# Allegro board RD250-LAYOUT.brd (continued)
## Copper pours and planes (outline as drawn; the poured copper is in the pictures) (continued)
VCC12R0_1 on BOTTOM: 133.45,6.1 133.34,6.14 133.3,6.25 133.3,6.7 133.34,6.81 133.45,6.85 134.6,6.85 134.71,6.81 134.75,6.7 134.75,6.25 134.71,6.14 134.6,6.1
VCC12R0_1 on BOTTOM: 184.25,51.55 184.16,51.57 184.02,51.71 184,51.8 184,52.75 184.01,52.83 184.05,52.9 184.05,56.35 179.27,61.12 179.22,61.2 179.2,61.3 179.2,70.95 179.16,71 179.15,71.06 179.15,71.35 179.19,71.46 179.3,71.5 179.6,71.5 179.71,71.46 179.75,71.35 179.75,71.06 179.74,71 179.71,70.96 179.7,61.4 184.48,56.63 184.53,56.55 184.55,56.45 184.55,52.9 184.59,52.83 184.6,52.75 184.6,51.8 184.53,51.62 184.35,51.55
VCC12R0_1 on BOTTOM: 97.09,65.55 96.99,65.59 96.94,65.67 96.9,65.95 96.9,66.29 96.9,66.32 96.97,66.75 96.97,67.19 96.51,68.25 96.59,68.45 96.79,68.37 96.96,67.97 97.44,67.97 97.61,68.37 97.81,68.45 97.89,68.25 97.35,67.02 97.35,65.95 97.35,65.91 97.31,65.67 97.26,65.59 97.16,65.55
VCC12R0_1 on CONDUCTIVE4: outline of 178 points within 96.77,4.43 203.15,103.79
VCC12R0_2 on TOP: 234.32,5.57 234.03,5.87 234.32,6.17 235.02,6.17 235.51,6.12 239.82,6.12 243.57,9.88 243.65,9.93 243.75,9.95 244.9,9.95 248.45,13.5 248.45,13.59 248.47,13.69 248.52,13.77 248.53,13.78 248.61,13.83 248.7,13.85 248.9,13.85 248.99,13.83 249.07,13.78 249.1,13.75 254,13.75 254.1,13.73 254.18,13.68 255.05,12.8 256.45,12.8 258.4,14.75 258.4,26.6 257.87,27.13 257.82,27.21 257.8,27.3 257.8,30.15 257.87,30.33 258.05,30.4 260.35,30.4 260.53,30.33 260.6,30.15 260.6,29.65 260.87,29.38 260.9,29.35 262.19,29.35 263.35,30.09 263.62,30.21 263.91,30.25 265.2,30.25 266.25,29.2 265.2,28.15 263.91,28.15 263.62,28.19 263.35,28.31 262.19,29.05 260.9,29.05 260.87,29.02 260.6,28.75 260.6,26.75 260.53,26.57 260.35,26.5 258.9,26.5 258.9,14.65 258.88,14.55 258.83,14.47 256.73,12.37 256.67,12.33 256.61,12.31 256.58,12.3 256.55,12.3 254.95,12.3 254.85,12.32 254.77,12.37 253.9,13.25 248.9,13.25 245.18,9.52 245.1,9.47 245,9.45 243.85,9.45 240.1,5.69 240.02,5.64 239.92,5.62 235.51,5.62 235.02,5.57
VCC12R0_2 on BOTTOM: 290.56,6.38 290.5,6.39 290.46,6.42 290.09,6.78 290.06,6.83 290.05,6.89 290.05,13.89 276.54,27.4 260.95,27.4 260.25,26.7 260.08,26.59 259.89,26.55 258.75,26.55 258.4,26.7 258.25,27.05 258.25,28.75 258.4,29.1 258.75,29.25 259.89,29.25 260.08,29.21 260.25,29.1 260.95,28.4 276.75,28.4 276.94,28.36 277.1,28.25 291.4,13.96 291.51,13.79 291.55,13.6 291.55,9 292.19,8.36 293.71,8.36 293.88,8.33 294.03,8.24 294.04,8.23 294.48,7.79 294.51,7.75 294.52,7.69 294.52,6.96 294.51,6.9 294.48,6.86 294.04,6.42 293.99,6.39 293.94,6.38
VCC12R0_2 on CONDUCTIVE3: outline of 82 points within 235.95,26.4 260.1,124.15
ACIN on BOTTOM: 108.92,19.79 108.81,19.8 107.7,20.24 107.68,20.24 106.7,19.84 106.58,19.81 106.47,19.8 106.09,19.8 105.49,20.4 106.09,21 106.47,21 106.58,20.99 106.7,20.96 107.7,20.55 107.71,20.55 108.7,20.95 108.81,20.98 108.92,20.99 109.3,20.99 109.9,20.39 109.3,19.79
CONN002 on TOP, BOTTOM: 169,84.85 168.89,84.89 168.85,85 168.85,87.2 168.89,87.31 169,87.35 171.2,87.35 171.31,87.31 171.35,87.2 171.35,85 171.31,84.89 171.2,84.85
CONN002 on TOP, BOTTOM: 144.66,84.85 144.55,84.89 144.51,85 144.51,87.2 144.55,87.31 144.66,87.35 146.86,87.35 146.97,87.31 147.01,87.2 147.01,85 146.97,84.89 146.86,84.85
CONN002 on CONDUCTIVE2, CONDUCTIVE5: 163.8,73.35 163.73,73.38 163.7,73.45 163.7,74.8 163.49,75.29 163,75.5 161.84,75.5 161.8,75.51 161.77,75.53 161.1,76.2 156.68,76.2 156.6,76.23 156.57,76.3 156.57,76.92 151.7,81.8 147.94,81.8 147.9,81.81 147.87,81.83 144.68,85.02 144.66,85.05 144.65,85.09 144.65,86.9 144.68,86.97 144.75,87 146.85,87 146.92,86.97 146.95,86.9 146.95,84.6 148.88,82.67 156.33,82.67 156.37,82.67 156.4,82.65 159.35,79.7 167.2,79.7 167.27,79.67 167.3,79.6 167.3,75.84 167.29,75.8 167.27,75.77 167.15,75.65 167.15,73.45 167.12,73.38 167.05,73.35
CONN002 on CONDUCTIVE3, CONDUCTIVE4: outline of 88 points within 143.97,62.8 200,112.1
CONN003 on BOTTOM: outline of 86 points within 169.15,84.9 199.95,129.4
CONN004 on TOP: 293.96,109.55 293.9,109.56 293.86,109.59 293.29,110.16 293.26,110.2 293.25,110.26 293.25,116.79 293.26,116.85 293.29,116.89 293.86,117.46 293.9,117.49 293.96,117.5 300.89,117.5 300.95,117.49 300.99,117.46 301.41,117.04 301.44,117 301.45,116.94 301.45,110.21 301.44,110.15 301.41,110.11 300.89,109.59 300.85,109.56 300.79,109.55
CONN004 on TOP: 305.6,44.85 305.49,44.89 305.45,45 305.45,46.64 305.44,46.7 305.41,46.74 302.82,49.33 294.51,49.33 294.45,49.34 294.41,49.37 293.14,50.63 293.11,50.68 293.1,50.74 293.1,69.84 293.11,69.9 293.14,69.94 293.76,70.56 293.8,70.59 293.86,70.6 303.65,70.6 303.76,70.56 303.8,70.45 303.8,63.25 306.2,60.85 314.95,60.85 315.06,60.81 315.1,60.7 315.1,49.55 315.36,49.29 315.39,49.25 315.4,49.19 315.4,45 315.36,44.89 315.25,44.85 312.35,44.85 312.24,44.89 312.2,45 312.2,46.7 311.9,47 309.05,47 308.7,46.65 308.7,45 308.66,44.89 308.55,44.85
CONN004 on TOP: 277.95,77 277.84,77.04 277.8,77.15 277.8,85.3 277.84,85.41 277.95,85.45 280.7,85.45 280.81,85.41 280.85,85.3 280.85,77.15 280.81,77.04 280.7,77
CONN004 on TOP: 278,123.1 277.89,123.14 277.85,123.25 277.85,131.4 277.89,131.51 278,131.55 280.7,131.55 280.81,131.51 280.85,131.4 280.85,123.25 280.81,123.14 280.7,123.1
CONN004 on BOTTOM: outline of 110 points within 278.75,44.85 317.95,129.3 ; 5 cut-outs
CONN004 on CONDUCTIVE3: 278.85,81.49 278.86,81.55 278.89,81.59 279.48,82.18 279.53,82.21 279.59,82.22 283.26,82.22 283.32,82.21 283.37,82.18 284.95,80.6 300.85,80.6 302.65,82.4 302.65,91.65 299.57,94.73 296.18,94.73 296.07,94.78 293.29,97.56 293.26,97.6 293.25,97.66 293.25,116.2 290.45,119 279.81,119 279.75,119.01 279.71,119.04 278.79,119.96 278.76,120 278.75,120.06 278.75,128.09 278.76,128.15 278.79,128.19 279.86,129.26 279.9,129.29 279.96,129.3 283.14,129.3 283.2,129.29 283.24,129.26 284.8,127.7 301.41,127.7 301.45,127.69 301.48,127.67 306.6,122.55 317.8,122.55 317.91,122.51 317.95,122.4 317.95,72.86 317.94,72.8 317.91,72.76 315.99,70.84 315.95,70.81 315.89,70.8 312.45,70.8 311.65,70 311.65,66.7 313.92,64.43 313.94,64.4 313.95,64.36 313.95,49.45 313.92,49.38 313.85,49.35 296.94,49.35 296.9,49.36 296.87,49.38 293.14,53.11 293.11,53.15 293.1,53.21 293.1,74.05 292.32,74.83 282.12,74.83 282.08,74.83 282.05,74.85 278.89,78.01 278.86,78.05 278.85,78.11 ; 5 cut-outs
CONN004 on CONDUCTIVE4: outline of 95 points within 278.75,44.85 317.95,129.3 ; 5 cut-outs
CS on BOTTOM: 245.85,42 245.74,42.04 245.7,42.15 245.7,45.2 245.74,45.31 245.85,45.35 248.3,45.35 248.41,45.31 248.45,45.2 248.45,42.15 248.41,42.04 248.3,42
CSB on BOTTOM: 131.71,85.24 131.71,85.6 131.43,86.25 131.41,86.35 131.41,87.2 131.62,87.58 132.05,87.61 132.44,87.43 132.55,87.43 132.75,87.63 132.8,87.66 132.86,87.67 133.04,87.67 133.42,87.79 133.46,87.8 133.5,87.8 133.7,87.8 133.97,87.53 133.7,87.25 133.5,87.25 133.46,87.25 133.42,87.26 133.04,87.38 132.96,87.38 132.68,87.1 132.64,87.06 132.31,86.91 132.31,86.35 132.3,86.25 132.05,85.68 132.05,85.36 132.16,84.98 132.17,84.91 132.14,84.85 132.06,84.79 131.95,84.8 131.94,84.81 131.9,84.79 131.86,84.79 131.82,84.79 131.67,84.83 131.64,84.98
FG1 on BOTTOM: 26.21,41.22 26.21,41.29 26.5,43.25 26.5,65.6 26.58,65.98 26.79,66.31 32.69,72.21 33.02,72.42 33.4,72.5 48.1,72.5 52.56,76.96 52.6,76.99 52.66,77 54.94,77 55,76.99 55.04,76.96 56.06,75.94 56.09,75.9 56.1,75.84 56.1,67.6 63.53,60.17 63.56,60.12 63.57,60.07 63.57,50.06 63.56,50 63.53,49.95 62.82,49.24 62.77,49.21 62.71,49.2 54.86,49.2 54.8,49.21 54.76,49.24 50.14,53.86 50.11,53.9 50.1,53.96 50.1,68.3 47.9,70.5 33.81,70.5 28.5,65.19 28.5,43.25 28.79,41.29 28.79,41.22 28.8,41.14 28.39,40.34 27.5,40.19 26.61,40.34 26.2,41.14
HS1_2 on BOTTOM (solid shape): 173.56,130 173.76,130.28 174.05,130.08 174.24,128.95 174.81,125.58 174.74,125.36 174.52,125.29 171.15,125.86 170.02,126.05 169.87,126.13 169.81,126.29 169.9,126.49 170.1,126.54 171.1,126.37 173.73,129
LGND on TOP: 267.05,64.3 266.94,64.34 266.9,64.45 266.9,67.7 265.44,69.16 265.41,69.2 265.4,69.26 265.4,69.7 265,70.1 262.5,70.1 262.39,70.14 262.35,70.25 262.35,73.15 262.39,73.26 262.5,73.3 263.4,73.3 263.75,73.65 263.75,74.24 263.76,74.3 263.79,74.34 264.21,74.76 264.25,74.79 264.31,74.8 265.75,74.8 267.05,76.1 267.05,76.15 267.09,76.26 267.2,76.3 270.55,76.3 270.66,76.26 270.7,76.15 270.7,66.11 270.69,66.05 270.66,66.01 268.99,64.34 268.95,64.31 268.89,64.3
LGND on TOP: 267.05,102.4 266.94,102.44 266.9,102.55 266.9,105.8 265.44,107.26 265.41,107.3 265.4,107.36 265.4,107.8 265,108.2 262.5,108.2 262.39,108.24 262.35,108.35 262.35,111.25 262.39,111.36 262.5,111.4 263.4,111.4 263.75,111.75 263.75,112.34 263.76,112.4 263.79,112.44 264.21,112.86 264.25,112.89 264.31,112.9 265.95,112.9 267.02,113.97 267.02,114.25 267.07,114.36 267.18,114.4 270.55,114.4 270.66,114.36 270.7,114.25 270.7,104.21 270.69,104.15 270.66,104.11 268.99,102.44 268.95,102.41 268.89,102.4
LGND on TOP: 242.81,15.7 242.75,15.71 242.71,15.74 241.2,17.25 238.31,17.25 238.25,17.26 238.21,17.29 237.89,17.61 237.86,17.65 237.85,17.71 237.85,21.74 237.86,21.8 237.89,21.84 238.11,22.06 238.15,22.09 238.21,22.1 241.84,22.1 241.9,22.09 241.94,22.06 243.9,20.1 248.19,20.1 248.25,20.09 248.29,20.06 248.8,19.55 255.35,19.55 255.46,19.51 255.5,19.4 255.5,15.85 255.46,15.74 255.35,15.7
LGND on TOP: 317.95,12.25 317.91,12.14 317.8,12.1 295.15,12.1 295.04,12.14 295,12.25 295,23.7 295.04,23.81 295.15,23.85 317.8,23.85 317.91,23.81 317.95,23.7 ; 1 cut-out
LGND on TOP: outline of 146 points within 262.15,49.83 317.9,134.45 ; 2 cut-outs
LGND on TOP: 266.85,4.9 266.74,4.94 266.7,5.05 266.7,11.95 266.74,12.06 266.85,12.1 267.76,12.1 267.85,12.07 267.9,12 272.5,7.4 272.53,7.35 272.54,7.3 272.54,5.55 272.53,5.49 272.5,5.44 272,4.94 271.95,4.91 271.89,4.9
LGND on BOTTOM: 269.06,5.45 269,5.46 268.96,5.49 267.45,7 266.25,7 266.14,7.04 266.1,7.15 266.1,7.45 266.14,7.56 266.25,7.6 266.8,7.6 267.1,7.9 267.1,8.54 267.11,8.6 267.14,8.64 267.16,8.66 267.2,8.69 267.26,8.7 268.14,8.7 268.2,8.69 268.24,8.66 269.5,7.4 271.84,7.4 271.9,7.39 271.94,7.36 272.21,7.09 272.24,7.05 272.25,6.99 272.25,5.96 272.24,5.9 272.21,5.86 271.84,5.49 271.8,5.46 271.74,5.45
LGND on BOTTOM: 246.9,80.05 246.79,80.09 246.75,80.2 246.75,81.35 246.79,81.46 246.9,81.5 247.99,81.5 248.05,81.49 248.09,81.46 248.55,81 250.25,81 251.4,82.15 251.4,82.95 250.91,83.44 244.06,83.44 244,83.45 243.96,83.48 243.83,83.61 243.8,83.65 243.79,83.71 243.79,84.14 243.8,84.2 243.83,84.24 243.91,84.32 243.95,84.35 244.01,84.36 251.73,84.36 251.79,84.35 251.83,84.32 252.16,83.99 252.19,83.95 252.2,83.89 252.2,80.71 252.19,80.65 252.16,80.61 252.04,80.49 252,80.46 251.94,80.45 248.55,80.45 248.19,80.09 248.15,80.06 248.09,80.05
LGND on BOTTOM: 246.9,118.15 246.79,118.19 246.75,118.3 246.75,119.45 246.79,119.56 246.9,119.6 247.99,119.6 248.05,119.59 248.09,119.56 248.55,119.1 250.25,119.1 251.4,120.25 251.4,121.05 250.91,121.54 244.06,121.54 244,121.55 243.96,121.58 243.83,121.71 243.8,121.75 243.79,121.81 243.79,122.24 243.8,122.3 243.83,122.34 243.91,122.42 243.95,122.45 244.01,122.46 251.73,122.46 251.79,122.45 251.83,122.42 252.16,122.09 252.19,122.05 252.2,121.99 252.2,118.81 252.19,118.75 252.16,118.71 252.04,118.59 252,118.56 251.94,118.55 248.55,118.55 248.19,118.19 248.15,118.16 248.09,118.15
LGND on BOTTOM: outline of 105 points within 262.35,107.25 305.6,134.5 ; 2 cut-outs
LGND on BOTTOM: 262.2,3 262.09,3.04 262.05,3.15 262.05,4.2 262.09,4.31 262.2,4.35 262.85,4.35 262.96,4.31 263,4.2 263,3.15 262.96,3.04 262.85,3
LGND on BOTTOM: 285.56,6.33 285.5,6.34 285.46,6.37 285.14,6.68 285.11,6.73 285.1,6.79 285.1,7.94 285.11,8 285.14,8.04 285.41,8.31 285.45,8.34 285.51,8.35 287.4,8.35 288.05,9 288.05,12.19 282.09,18.15 257,18.15 254.89,16.04 254.85,16.01 254.79,16 240.91,16 240.85,16.01 240.81,16.04 239.25,17.6 238.31,17.6 238.25,17.61 238.21,17.64 238.06,17.79 238.03,17.83 238.02,17.89 238.02,21.24 238.03,21.3 238.06,21.34 238.41,21.69 238.46,21.72 238.52,21.74 239.29,21.74 239.35,21.72 239.39,21.69 240.64,20.45 257.19,20.45 257.25,20.43 257.3,20.4 258.55,19.15 282.3,19.15 282.43,19.13 282.65,19 288.9,12.76 289.01,12.59 289.05,12.4 289.05,8.74 289.41,7.49 289.41,7.46 289.42,7.4 289.42,6.81 289.41,6.75 289.38,6.71 289.04,6.37 289,6.34 288.94,6.33
LGND on BOTTOM: outline of 114 points within 262.35,69.15 301.65,96 ; 2 cut-outs
LGND on BOTTOM: 249.5,2.4 249.39,2.44 249.35,2.55 249.35,6.25 249.39,6.36 249.5,6.4 251.05,6.4 251.16,6.36 251.2,6.25 251.2,2.55 251.16,2.44 251.05,2.4
LGND on BOTTOM: 258.65,119 258.54,119.04 258.5,119.15 258.5,122.85 258.54,122.96 258.65,123 261.7,123 261.81,122.96 261.85,122.85 261.85,119.15 261.81,119.04 261.7,119
LGND on BOTTOM: 287.3,23 287.19,23.04 287.15,23.15 287.15,24.85 287.19,24.96 287.3,25 289.3,25 289.41,24.96 289.45,24.85 289.45,23.15 289.41,23.04 289.3,23
LGND on BOTTOM: 258.65,80.9 258.54,80.94 258.5,81.05 258.5,84.4 258.54,84.51 258.65,84.55 261.7,84.55 261.81,84.51 261.85,84.4 261.85,81.05 261.81,80.94 261.7,80.9
LGND on CONDUCTIVE2, CONDUCTIVE5: 246,86.98 246.03,87.05 246.1,87.08 253.93,87.08 256.62,89.77 256.65,89.79 256.69,89.8 261.95,89.8 262.35,90.2 262.35,94.5 262.38,94.57 262.45,94.6 265.2,94.6 265.27,94.57 265.3,94.5 265.3,70.2 265.27,70.13 265.2,70.1 262.45,70.1 262.38,70.13 262.35,70.2 262.35,74.7 261.75,75.3 256.84,75.3 256.8,75.31 256.77,75.33 256.63,75.47 256.61,75.5 256.6,75.54 256.6,77.7 255.15,79.15 252.24,79.15 252.2,79.16 252.17,79.18 250.93,80.42 250.91,80.45 250.9,80.49 250.9,83 250.45,83.45 246.1,83.45 246.03,83.48 246,83.55 ; 2 cut-outs
LGND on CONDUCTIVE2, CONDUCTIVE5: 245.2,79.85 245.13,79.88 245.1,79.95 245.1,82.35 245.13,82.42 245.2,82.45 250.1,82.45 250.17,82.42 250.2,82.35 250.2,79.95 250.17,79.88 250.1,79.85
LGND on CONDUCTIVE2, CONDUCTIVE5: outline of 187 points within 233.95,0.6 317.95,134.45 ; 51 cut-outs
LGND on CONDUCTIVE2, CONDUCTIVE5: 246,125.08 246.03,125.15 246.1,125.17 253.93,125.17 256.62,127.87 256.65,127.89 256.69,127.9 260.45,127.9 262.35,129.8 262.35,132.6 262.38,132.67 262.45,132.7 265.2,132.7 265.27,132.67 265.3,132.6 265.3,108.3 265.27,108.23 265.2,108.2 262.45,108.2 262.38,108.23 262.35,108.3 262.35,112.15 261.1,113.4 256.84,113.4 256.8,113.41 256.77,113.43 256.63,113.57 256.61,113.6 256.6,113.64 256.6,115.8 255.15,117.25 252.24,117.25 252.2,117.26 252.17,117.28 250.93,118.52 250.91,118.55 250.9,118.59 250.9,121.1 250.45,121.55 246.1,121.55 246.03,121.58 246,121.65 ; 2 cut-outs
LGND on CONDUCTIVE2, CONDUCTIVE5: 245.2,117.95 245.13,117.98 245.1,118.05 245.1,120.45 245.13,120.52 245.2,120.55 250.1,120.55 250.17,120.52 250.2,120.45 250.2,118.05 250.17,117.98 250.1,117.95
Net_1 on BOTTOM: 309.56,124.35 309.5,124.36 309.46,124.39 307.4,126.45 307.37,126.49 307.36,126.55 307.36,129.97 307.37,130.03 307.4,130.08 309.33,132 309.38,132.04 309.44,132.05 313.49,132.05 313.55,132.04 313.6,132 315.51,130.09 315.54,130.05 315.55,129.99 315.55,126.56 315.54,126.5 315.51,126.46 313.44,124.39 313.4,124.36 313.34,124.35
PFC_OFF on BOTTOM: 143.28,9.53 143.24,9.53 142.94,9.57 142.47,9.57 142.42,9.59 142.37,9.62 141.09,10.89 141.06,10.94 141.05,11 141.05,11.6 140.9,11.75 139.94,11.75 139.07,11.25 139.04,11.24 139,11.23 138.86,11.34 138.93,11.51 139.29,11.72 139.29,12.08 138.93,12.29 138.86,12.46 139,12.57 139.04,12.56 139.07,12.55 139.94,12.05 140.9,12.05 141.05,12.2 141.05,12.92 140.98,13.25 140.97,13.3 140.97,13.47 141.2,13.7 141.43,13.47 141.43,13.3 141.42,13.25 141.35,12.92 141.35,11.06 142.54,9.88 142.94,9.88 143.24,9.92 143.28,9.93 143.97,9.93 144.18,9.72 143.97,9.53
PFC_OUT on CONDUCTIVE3 (solid shape): 166.91,30.85 167.04,31.02 167.21,30.9 167.72,27.65 167.68,27.52 167.55,27.48 164.3,27.99 164.18,28.16 164.35,28.29 165.09,28.17 167.03,30.11
PFC_OUT on TOP: 95.7,130.15 95.59,130.19 95.55,130.3 95.55,133 95.59,133.11 95.7,133.15 98.1,133.15 98.21,133.11 98.25,133 98.25,130.3 98.21,130.19 98.1,130.15
PFC_OUT on TOP: 170.74,59.35 170.63,59.39 170.59,59.5 170.59,61.7 170.63,61.81 170.74,61.85 172.94,61.85 173.05,61.81 173.09,61.7 173.09,59.5 173.05,59.39 172.94,59.35
PFC_OUT on TOP: 139.54,59.35 139.43,59.39 139.39,59.5 139.39,61.7 139.43,61.81 139.54,61.85 141.74,61.85 141.85,61.81 141.89,61.7 141.89,59.5 141.85,59.39 141.74,59.35
PFC_OUT on BOTTOM: outline of 164 points within 91.75,22.4 222.12,133.15
PN on TOP: 152.25,116.6 152.14,116.64 152.1,116.75 152.1,118.25 152.14,118.36 152.25,118.4 153,118.4 153.7,119.1 153.7,120.35 153.74,120.46 153.85,120.5 154.15,120.5 154.26,120.46 154.3,120.35 154.3,118.26 154.29,118.2 154.26,118.16 153.95,117.85 153.95,116.75 153.91,116.64 153.8,116.6
PN on TOP: 116.35,59.35 116.24,59.39 116.2,59.5 116.2,61.7 116.24,61.81 116.35,61.85 118.55,61.85 118.66,61.81 118.7,61.7 118.7,59.5 118.66,59.39 118.55,59.35
PN on TOP: 188.8,44.45 188.65,44.6 187.3,44.6 187.2,44.62 185.22,46.57 185.17,46.65 185.15,46.75 185.15,49.7 185.19,49.81 185.3,49.85 185.6,49.85 185.71,49.81 185.75,49.7 185.75,46.75 187.35,45.15 189.1,45.15 189.21,45.11 189.25,45 189.25,43.75 189.03,43.52 188.8,43.75
PN on TOP: 176.16,72.4 176.1,72.41 176.06,72.44 175.68,72.83 174.69,72.83 174.63,72.84 174.58,72.87 174.1,73.35 173.05,73.35 172.94,73.39 172.9,73.5 172.9,75 172.94,75.11 173.05,75.15 174.64,75.15 174.7,75.14 174.74,75.11 175.85,74 176.65,74 176.76,73.96 176.8,73.85 176.8,72.55 176.76,72.44 176.65,72.4
PN on TOP: 147.56,59.35 147.45,59.39 147.41,59.5 147.41,61.7 147.45,61.81 147.56,61.85 149.76,61.85 149.87,61.81 149.91,61.7 149.91,59.5 149.87,59.39 149.76,59.35
PN on TOP: 163.56,84.85 163.45,84.89 163.41,85 163.41,87.2 163.45,87.31 163.56,87.35 165.76,87.35 165.87,87.31 165.91,87.2 165.91,85 165.87,84.89 165.76,84.85
PN on TOP: 143.86,106.8 143.8,106.81 143.76,106.84 143.19,107.41 143.16,107.45 143.15,107.51 143.15,108.05 143.19,108.16 143.3,108.2 144.7,108.2 144.81,108.16 144.85,108.05 144.85,106.95 144.81,106.84 144.7,106.8
PN on TOP: 148.95,43.25 148.84,43.29 148.8,43.4 148.8,47.45 148.49,47.76 146.56,47.76 146.2,47.4 146.2,45.05 146.66,44.59 146.69,44.55 146.7,44.49 146.7,44.15 146.66,44.04 146.55,44 145.45,44 145.34,44.04 145.3,44.15 145.3,45.14 145.31,45.2 145.34,45.24 145.65,45.55 145.65,47.4 145.29,47.76 145.26,47.8 145.25,47.86 145.25,48.65 145.29,48.76 145.4,48.8 149.35,48.8 149.46,48.76 149.5,48.65 149.5,47.85 149.66,47.69 149.69,47.65 149.7,47.59 149.7,43.4 149.66,43.29 149.55,43.25
PN on TOP: 149.05,105.15 148.94,105.19 148.9,105.3 148.9,106.09 148.91,106.15 148.94,106.19 149.4,106.65 149.4,107.9 147.94,109.36 147.91,109.4 147.9,109.46 147.9,110.65 147.09,111.46 147.06,111.5 147.05,111.56 147.05,113.15 147.09,113.26 147.2,113.3 148.7,113.3 148.81,113.26 148.85,113.15 148.85,111.35 149.13,111.07 149.16,111.02 149.18,110.96 149.18,110.08 149.45,109.8 151.1,109.8 151.21,109.76 151.25,109.65 151.25,108.66 151.24,108.6 151.21,108.56 150.3,107.65 150.3,106.65 151.11,105.84 151.14,105.8 151.15,105.74 151.15,105.51 151.14,105.45 151.11,105.41 150.89,105.19 150.85,105.16 150.79,105.15
PN on TOP, BOTTOM: 162.14,130.55 162.03,130.59 161.99,130.7 161.99,132.9 162.03,133.01 162.14,133.05 164.34,133.05 164.45,133.01 164.49,132.9 164.49,130.7 164.45,130.59 164.34,130.55
PN on TOP, BOTTOM: 120.7,130.15 120.59,130.19 120.55,130.3 120.55,133 120.59,133.11 120.7,133.15 123.1,133.15 123.21,133.11 123.25,133 123.25,130.3 123.21,130.19 123.1,130.15
PN on BOTTOM: 132.05,3.5 131.94,3.54 131.9,3.65 131.9,5.35 131.94,5.46 132.05,5.5 133.05,5.5 133.16,5.46 133.2,5.35 133.2,4.41 133.19,4.35 133.16,4.31 132.39,3.54 132.35,3.51 132.29,3.5
PN on BOTTOM: 153.18,10.05 153.07,10.09 153.03,10.2 153.03,10.43 153.02,10.49 153,10.59 153,13.65 153.04,13.76 153.15,13.8 154.2,13.8 154.31,13.76 154.35,13.65 154.35,10.2 154.31,10.09 154.2,10.05
PN on BOTTOM: 163.56,84.85 163.45,84.89 163.41,85 163.41,86.17 163.4,86.19 163.4,86.22 163.4,87.14 163.4,87.17 163.41,87.2 163.45,87.3 163.55,87.35 163.7,87.5 163.7,88.05 162.74,89.01 162.71,89.05 162.7,89.11 162.7,93.29 162.71,93.35 162.74,93.39 163.01,93.66 163.05,93.69 163.11,93.7 164.59,93.7 164.65,93.69 164.69,93.66 165.85,92.5 174.1,92.5 174.16,92.49 175.31,91.35 177.17,91.35 177.5,91.42 177.55,91.42 177.72,91.42 177.95,91.2 177.72,90.97 177.55,90.97 177.5,90.98 177.17,91.05 175.25,91.05 175.19,91.06 175.14,91.09 174.04,92.2 165.81,92.2 165.43,91.82 165.43,91 166.16,90.28 169.27,90.28 169.6,90.34 169.65,90.35 169.82,90.35 170.05,90.12 169.82,89.9 169.65,89.9 169.6,89.91 169.27,89.97 166.36,89.97 165.5,89.12 165.5,87.5 165.65,87.35 165.76,87.35 165.87,87.31 165.91,87.2 165.91,85 165.87,84.89 165.76,84.85
PN on BOTTOM: 220.55,0.8 220.44,0.84 220.4,0.95 220.4,1.89 220.41,1.95 220.44,1.99 221.31,2.86 221.35,2.89 221.41,2.9 224.15,2.9 224.26,2.86 224.3,2.75 224.3,0.95 224.26,0.84 224.15,0.8
PN on BOTTOM: 208.7,8.15 208.61,8.17 208.53,8.22 208.22,8.53 208.17,8.61 208.15,8.7 208.15,10 207.77,10.37 207.75,10.4 207.73,10.44 207.71,10.49 207.7,10.55 207.7,15.35 207.55,15.97 207.55,16.02 207.55,16.55 207.95,16.95 208.35,16.55 208.35,16.02 208.35,15.97 208.34,15.93 208.2,15.35 208.2,10.65 208.35,10.5 208.65,10.5 208.88,10.73 208.96,10.78 209.05,10.8 210.6,10.8 210.69,10.78 210.77,10.73 210.95,10.55 212.95,10.55 213.06,10.51 213.1,10.4 213.1,9.51 213.09,9.45 213.06,9.41 212.95,9.3 212.95,8.4 212.88,8.22 212.7,8.15
PN on BOTTOM: 174.25,73.8 174.14,73.84 174.1,73.95 174.1,76.2 174.14,76.31 174.25,76.35 178.7,76.35 178.81,76.31 178.85,76.2 178.85,75.15 178.81,75.04 178.7,75 178.16,75 178.1,75.01 178.06,75.04 177.7,75.4 175.9,75.4 174.75,74.25 174.75,73.95 174.71,73.84 174.6,73.8
PN on BOTTOM: 149.31,50.55 149.25,50.56 149.21,50.59 147.44,52.36 147.41,52.4 147.4,52.46 147.4,61.15 147.4,61.18 147.41,61.2 147.41,61.7 147.45,61.81 147.56,61.85 149.76,61.85 149.87,61.81 149.91,61.7 149.91,59.5 149.91,59.47 149.9,59.45 149.9,57.15 153,54.05 162.9,54.05 163.01,54.01 163.05,53.9 163.05,50.7 163.01,50.59 162.9,50.55
PN on BOTTOM: 179.22,121.35 176.85,121.35 176.74,121.39 176.7,121.5 176.7,121.9 176.74,122.01 176.85,122.05 179.22,122.05 180.13,122.51 180.36,122.47 180.46,122.27 180.43,122.15 180.35,122.06 180.32,122.05 179.86,121.81 179.86,121.59 180.32,121.35 180.43,121.26 180.46,121.13 180.43,121.01 180.34,120.91 180.22,120.88 180.1,120.91
PN on BOTTOM: 210.26,4.15 210.2,4.16 210.16,4.19 209.65,4.7 208.85,4.7 208.74,4.74 208.7,4.85 208.7,6.55 208.74,6.66 208.85,6.7 211.14,6.7 211.2,6.69 211.24,6.66 211.56,6.34 211.59,6.3 211.6,6.24 211.6,4.46 211.59,4.4 211.56,4.36 211.39,4.19 211.35,4.16 211.29,4.15
PN on BOTTOM: 128.4,8.08 128.4,8.11 128.44,8.35 128.27,8.52 128.24,8.57 128.22,8.62 128.22,8.72 128.21,8.8 127.75,8.8 127.39,8.44 127.35,8.41 127.29,8.4 122.46,8.4 122.4,8.41 122.36,8.44 122.09,8.71 122.06,8.75 122.05,8.81 122.05,13 121.19,13.86 121.16,13.9 121.15,13.96 121.15,14.85 121.19,14.96 121.3,15 123.6,15 123.71,14.96 123.75,14.85 123.75,10.55 124.1,10.2 128.45,10.2 128.56,10.16 128.6,10.05 128.6,8.61 128.71,8.51 128.73,8.47 128.75,8.42 128.8,8.11 128.8,8.08 128.8,7.78 128.6,7.58 128.4,7.78
PN on BOTTOM: 134.81,8.9 134.75,8.91 134.71,8.94 134.44,9.21 134.41,9.25 134.4,9.31 134.4,9.79 134.41,9.85 134.44,9.89 134.61,10.06 134.65,10.09 134.71,10.1 140.25,10.1 140.36,10.06 140.4,9.95 140.4,9.05 140.36,8.94 140.25,8.9
PN on BOTTOM: 117.56,50.15 117.5,50.16 117.46,50.19 116.24,51.41 116.21,51.45 116.2,51.51 116.2,60.82 116.2,60.85 116.21,60.88 116.21,61.7 116.25,61.81 116.36,61.85 118.56,61.85 118.67,61.81 118.71,61.7 118.71,59.5 118.71,59.47 118.7,59.45 118.7,58.69 118.69,58.64 118.66,58.59 117.97,57.9 117.97,55.7 118.29,55.38 118.42,55.38 118.48,55.36 118.52,55.33 118.56,55.3 118.59,55.25 118.6,55.19 118.6,54.98 118.56,54.88 118.45,54.83 118.25,54.83 117.97,54.55 117.97,53.18 118.7,52.45 124.8,52.45 126.01,53.66 126.05,53.69 126.11,53.7 132.6,53.7 132.71,53.66 132.75,53.55 132.75,50.3 132.71,50.19 132.6,50.15
PN on BOTTOM: 143.85,0.95 143.74,0.99 143.7,1.1 143.7,1.3 143.74,1.41 143.85,1.45 144.2,1.45 144.44,1.53 144.6,1.73 144.61,1.76 144.63,1.78 144.9,2.05 144.9,3.05 144.94,3.16 145.05,3.2 148.5,3.2 148.54,3.2 148.7,3.18 148.86,3.2 148.9,3.2 150.14,3.2 150.2,3.19 150.24,3.16 150.55,2.85 151.35,2.85 151.46,2.81 151.5,2.7 151.5,1.81 151.49,1.75 151.46,1.71 151.24,1.49 151.2,1.46 151.14,1.45 145.45,1.45 144.99,0.99 144.95,0.96 144.89,0.95
PN on BOTTOM: 179.4,53.85 179.29,53.89 179.25,54 179.25,54.9 179.5,55.15 179.75,54.9 179.75,54 179.71,53.89 179.6,53.85
PN on BOTTOM: 163.56,17.25 163.5,17.26 163.46,17.29 161.94,18.81 161.91,18.85 161.9,18.91 161.9,22.24 161.91,22.3 161.94,22.34 163.61,24.01 163.65,24.04 163.71,24.05 169.69,24.05 169.75,24.04 169.79,24.01 172.16,21.64 172.19,21.6 172.2,21.54 172.2,17.4 172.16,17.29 172.05,17.25
PN on BOTTOM: 197.26,16.83 197.26,16.86 197.23,16.86 197.21,16.86 197.1,16.96 197.12,17.09 197.14,17.12 197.17,17.14 197.5,17.32 197.5,21.09 197.39,21.2 197.26,21.2 197.2,21.16 197.2,18.4 197.16,18.29 197.05,18.25 195.61,18.25 195.55,18.26 195.51,18.29 193.43,20.38 192.54,20.38 192.48,20.39 192.43,20.42 192.09,20.76 192.06,20.8 192.05,20.86 192.05,22.09 192.06,22.15 192.09,22.19 192.51,22.61 192.55,22.64 192.61,22.65 193.5,22.65 195.46,24.61 195.5,24.64 195.56,24.65 197.05,24.65 197.16,24.61 197.2,24.5 197.2,21.74 197.44,21.57 197.46,21.56 197.79,21.21 197.8,21.15 197.8,17.25 197.79,17.19 197.72,17.11 197.54,16.77 197.52,16.74 197.49,16.72 197.36,16.7 197.26,16.81
PN on BOTTOM: 91.96,64.2 91.9,64.21 91.86,64.24 91.04,65.06 91.01,65.1 91,65.16 91,65.79 91.01,65.85 91.04,65.89 92.01,66.86 92.05,66.89 92.11,66.9 93.25,66.9 93.36,66.86 93.4,66.75 93.4,64.35 93.36,64.24 93.25,64.2
PN on CONDUCTIVE2, CONDUCTIVE5: 175.15,64 175.12,63.93 175.05,63.9 164.69,63.9 164.65,63.91 164.62,63.93 162.68,65.87 162.66,65.9 162.65,65.94 162.65,70 162.68,70.07 162.75,70.1 175.05,70.1 175.12,70.07 175.15,70 ; 3 cut-outs
PN on CONDUCTIVE2, CONDUCTIVE5: outline of 467 points within 80.49,0.55 223.4,133.85 ; 52 cut-outs
RY_OFF on BOTTOM: 128.8,2.84 128.69,2.89 128.65,2.99 128.65,3.29 128.66,3.35 128.69,3.39 129.05,3.75 129.05,6.15 129.09,6.26 129.2,6.3 130.15,6.3 132.36,8.51 132.4,8.54 132.46,8.55 133.05,8.55 133.16,8.51 133.2,8.4 133.2,7.36 133.19,7.3 133.16,7.25 131.51,5.6 131.51,3.81 131.49,3.75 131.46,3.71 130.64,2.89 130.6,2.86 130.54,2.84
RY_OFF on BOTTOM: 96.1,64.2 95.99,64.24 95.95,64.35 95.95,66.3 95.99,66.41 96.1,66.45 96.4,66.45 96.51,66.41 96.55,66.3 96.55,64.35 96.51,64.24 96.4,64.2
SIG1 on BOTTOM (solid shape): 44.82,29.34 44.98,29.3 45.01,29.15 44.14,26.48 44.09,26.41 44,26.38 43.88,26.44 43.85,26.57 44.04,27.15 42.83,28.37 42.25,28.18 42.06,28.28 42.15,28.47 42.82,28.69
SIG1 on TOP: 34.9,25.21 34.85,25.22 34.8,25.25 32.14,27.91 32.11,27.95 32.1,28.01 32.1,36.45 32.11,36.51 32.14,36.56 34.7,39.12 34.7,53.09 34.71,53.15 34.74,53.19 35.71,54.16 35.75,54.19 35.81,54.2 37.84,54.2 37.9,54.19 37.94,54.16 39.66,52.44 39.69,52.4 39.7,52.34 39.7,37.11 39.69,37.05 39.66,37 37.1,34.44 37.1,31.47 37.97,30.61 43.11,30.61 43.17,30.6 43.22,30.56 44.35,29.43 44.38,29.38 44.39,29.32 44.39,26.21 44.38,26.15 44.35,26.1 43.5,25.25 43.45,25.22 43.4,25.21
SIG2 on BOTTOM (solid shape): 43.85,17.37 43.95,17.56 44.14,17.46 44.36,16.79 45.01,14.79 44.98,14.64 44.82,14.6 42.15,15.47 42.08,15.53 42.05,15.62 42.11,15.74 42.25,15.76 42.83,15.57 44.04,16.79
SIG2 on TOP: 30.87,14.03 30.82,14.04 30.77,14.08 18.73,26.11 18.19,26.92 18,27.88 18,34.54 18.01,34.6 18.04,34.64 19.16,35.76 19.2,35.79 19.26,35.8 21.64,35.8 21.7,35.79 21.74,35.76 22.96,34.54 22.99,34.5 23,34.44 23,28.92 32.52,19.4 43.17,19.4 43.23,19.39 43.28,19.36 44.16,18.48 44.19,18.43 44.2,18.37 44.2,15.63 44.19,15.57 44.16,15.53 42.71,14.08 42.66,14.04 42.6,14.03
SIG6 on BOTTOM (solid shape): 98.28,18.23 98.15,18.4 98.32,18.53 100.67,18.23 100.79,18.14 100.77,17.99 99.74,16.54 99.4,16.06 99.34,16.01 99.27,15.99 99.14,16.08 99.15,16.23 99.45,16.65 98.78,18.17
SIG6 on TOP: 103.1,24.89 103.1,70.66 98.76,75 74.6,75 73.64,75.19 72.83,75.73 70.83,77.73 70.29,78.54 70.1,79.5 70.1,110.45 70.29,111.41 70.83,112.22 78.43,119.82 79.24,120.36 80.2,120.55 108.6,120.55 111.7,123.65 111.7,131.65 114.2,134.15 116.7,131.65 116.7,115.3 116.51,114.34 115.97,113.53 109.98,107.54 109.93,107.51 109.87,107.5 107.96,107.5 107.9,107.51 107.86,107.54 106.64,108.76 106.61,108.8 106.6,108.86 106.6,113.95 105,115.55 81.24,115.55 75.1,109.41 75.1,80.54 75.64,80 99.8,80 100.76,79.81 101.57,79.27 108.06,72.78 108.09,72.73 108.1,72.67 108.1,22.88 108.09,22.82 108.06,22.77 100.49,15.2 99.68,14.66 98.72,14.47 98.11,14.47 95.62,16.73 97.64,19.42
SIG6 on BOTTOM: 113.2,130.15 113.09,130.19 113.05,130.3 113.05,133 113.09,133.11 113.2,133.15 115.6,133.15 115.71,133.11 115.75,133 115.75,130.3 115.71,130.19 115.6,130.15
SIG8 on TOP, BOTTOM: 105.7,130.15 105.59,130.19 105.55,130.3 105.55,133 105.59,133.11 105.7,133.15 108.1,133.15 108.21,133.11 108.25,133 108.25,130.3 108.21,130.19 108.1,130.15
SIG8 on BOTTOM: 106.5,13.39 105.9,13.99 106.5,14.59 106.88,14.59 106.99,14.58 108.04,14.17 108.05,14.17 108.14,14.17 108.37,14.4 108.65,14.84 108.67,14.87 108.69,14.89 108.83,14.91 108.92,14.8 108.92,14.77 108.92,14.74 108.95,14.74 108.98,14.74 109.09,14.65 109.07,14.51 109.05,14.49 109.02,14.47 108.58,14.19 108.34,13.95 108.23,13.87 108.1,13.84 107.1,13.44 106.99,13.4 106.88,13.39
SIG8 on BOTTOM: 70.71,44.59 70.65,44.6 70.6,44.63 69.99,45.25 69.96,45.3 69.94,45.35 69.94,64.79 69.95,64.85 69.99,64.9 80.78,75.69 80.78,84.93 78.83,86.87 78.29,87.68 78.1,88.64 78.1,103.2 80.6,105.7 83.1,103.2 83.1,89.67 85.04,87.73 85.59,86.92 85.78,85.96 85.78,74.65 85.59,73.7 85.04,72.88 77,64.84 77,56.63 89.8,56.63 89.86,56.62 89.91,56.58 90.8,55.69 90.83,55.64 90.85,55.58 90.85,51.6 90.83,51.55 90.8,51.5 90.28,50.98 90.24,50.95 90.18,50.94 88.11,50.94 88.05,50.95 88.01,50.98 86.69,52.3 77.5,52.3 75.28,50.08 75.28,45.2 75.27,45.14 75.24,45.09 74.78,44.63 74.73,44.6 74.67,44.59
SIG9 on BOTTOM: 48.31,24.95 48.33,25.05 48.39,25.13 48.95,25.69 48.95,26.33 48.76,27.02 48.75,27.08 48.75,27.14 49.2,27.59 49.65,27.14 49.65,27.08 49.64,27.02 49.63,26.96 49.45,26.33 49.45,25.69 50.01,25.13 50.07,25.05 50.09,24.95 50.09,24.01 49.84,23.76 49.59,24.01 49.59,24.85 49.29,25.14 49.11,25.14 48.81,24.85 48.81,24.01 48.56,23.76 48.31,24.01
SIG10 on BOTTOM: 48.95,15.99 48.96,16.05 48.97,16.11 49.15,16.74 49.15,16.79 48.39,17.55 48.33,17.63 48.31,17.73 48.31,18.79 48.56,19.04 48.81,18.79 48.81,17.83 49.3,17.35 49.5,17.35 49.59,17.43 49.59,18.79 49.84,19.04 50.09,18.79 50.09,17.32 50.07,17.23 50.01,17.15 49.65,16.79 49.65,16.74 49.84,16.05 49.85,15.99 49.85,15.66 49.4,15.21 48.95,15.66
SIG11 on TOP: 165.66,59.35 165.55,59.39 165.51,59.5 165.51,61.7 165.55,61.81 165.66,61.85 167.86,61.85 167.97,61.81 168.01,61.7 168.01,59.5 167.97,59.39 167.86,59.35
SIG11 on BOTTOM: 165.94,59.87 165.89,59.88 165.84,59.91 165.53,60.22 165.5,60.27 165.49,60.32 165.49,60.87 162.5,63.85 160.86,63.85 160.8,63.86 160.76,63.89 151.85,72.8 148.21,72.8 148.15,72.81 148.11,72.84 146.89,74.06 146.86,74.1 146.85,74.16 146.85,77.65 146.89,77.76 147,77.8 148.99,77.8 149.05,77.79 149.09,77.76 150.55,76.3 153.34,76.3 153.4,76.29 153.44,76.26 162.55,67.15 163.9,67.15 163.96,67.14 167.68,63.44 167.71,63.39 167.72,63.33 167.72,60.35 167.71,60.29 167.68,60.24 167.34,59.91 167.3,59.88 167.24,59.87
SIG12 on TOP: 134.46,59.35 134.35,59.39 134.31,59.5 134.31,61.7 134.35,61.81 134.46,61.85 136.66,61.85 136.77,61.81 136.81,61.7 136.81,59.5 136.77,59.39 136.66,59.35
SIG0012 on TOP: 96.38,25.28 96.33,25.29 96.28,25.32 94.8,26.79 94.77,26.84 94.76,26.9 94.76,31.05 82.82,43 80.24,43 80.19,43.01 80.14,43.04 78.35,44.83 78.31,44.88 78.3,44.94 78.3,47.21 78.31,47.27 78.35,47.32 78.98,47.96 79.03,47.99 79.09,48 95.04,48 96.53,49.49 96.58,49.52 96.64,49.53 98.04,49.53 98.1,49.52 98.15,49.49 99.8,47.83 99.83,47.79 99.85,47.73 99.85,26.52 99.83,26.46 99.8,26.41 98.71,25.32 98.66,25.29 98.6,25.28
SIG12 on BOTTOM: 134.51,59.7 134.45,59.71 134.41,59.74 133.39,60.76 133.36,60.81 133.35,60.86 133.35,65.26 125.31,73.3 122.9,73.3 121.66,73.81 121.15,75.05 121.15,89.53 117.38,93.3 110.75,93.3 110.08,93.43 109.51,93.81 109.51,93.81 101.36,101.96 101.36,101.96 101.36,104.44 103.84,104.44 103.84,104.44 111.47,96.8 118.1,96.8 118.77,96.67 119.34,96.29 124.14,91.49 124.52,90.92 124.65,90.25 124.65,78.91 136.81,66.75 136.84,66.71 136.85,66.65 136.85,60.41 136.84,60.36 136.81,60.31 136.24,59.74 136.2,59.71 136.14,59.7
SIG0012 on BOTTOM: 95.61,35.76 94.82,36.56 92.98,36.56 92.02,36.75 91.21,37.29 91.21,37.29 84.1,44.4 80.4,44.4 80.34,44.41 80.3,44.44 79.88,44.86 79.85,44.91 79.83,44.97 79.83,47.93 79.85,47.99 79.88,48.04 81.19,49.36 81.24,49.39 81.3,49.4 85.14,49.4 86.09,49.21 86.91,48.67 94.01,41.56 94.79,41.56 95.61,42.38 95.61,46.6 95.43,46.78 95.43,50.32 98.97,50.32 99.88,49.4 100.42,48.59 100.61,47.64 100.61,39.06 100.61,38.96 100.61,38.86 100.61,26.97 98.11,24.47 95.61,26.97
SIG18 on TOP: 153,59.35 152.89,59.39 152.85,59.5 152.85,61.7 152.89,61.81 153,61.85 155.2,61.85 155.31,61.81 155.35,61.7 155.35,59.5 155.31,59.39 155.2,59.35
SIG18 on BOTTOM: 153.14,59.5 153.08,59.51 153.03,59.54 152.46,60.12 152.43,60.17 152.42,60.22 152.42,63.43 147.41,68.44 147.37,68.49 147.36,68.55 147.36,69.5 147.37,69.56 147.41,69.61 147.91,70.11 147.95,70.14 148.01,70.15 150.59,70.15 150.65,70.14 150.69,70.11 155.28,65.52 155.66,64.94 155.79,64.28 155.79,60.15 155.78,60.09 155.75,60.04 155.25,59.54 155.2,59.51 155.14,59.5
SIG22 on TOP: 121.79,59.35 121.68,59.39 121.64,59.5 121.64,61.7 121.68,61.81 121.79,61.85 123.99,61.85 124.1,61.81 124.14,61.7 124.14,59.5 124.1,59.39 123.99,59.35
SIG23 on TOP: 162.84,50.44 162.73,50.45 162.63,50.48 161.92,50.75 161.61,50.75 161.02,50.6 160.96,50.59 160.91,50.59 160.6,50.59 160.27,50.75 160.2,51.11 160.2,53.3 160.6,53.7 161,53.3 161,51.41 161.02,51.4 161.51,51.27 161.85,51.27 162.73,51.6 162.84,51.61 163.2,51.61 163.78,51.02 163.2,50.44
SIG27 on TOP: 133,51.29 132.94,51.32 132.88,51.37 132.85,51.4 132.52,51.4 131.6,51.22 131.54,51.22 131.07,51.22 130.49,51.8 131.07,52.38 131.54,52.38 131.6,52.38 131.66,52.37 132.52,52.2 132.9,52.2 132.93,52.23 133.06,52.32 133.22,52.35 133.35,52.35 133.61,52.25 133.75,52 133.79,51.9 133.8,51.8 133.8,49.7 133.4,49.3 133,49.7
SIG30 on TOP: 138.66,47.75 138.67,47.81 138.79,48.08 138.8,48.11 138.8,48.48 138.42,49.27 138.4,49.4 138.4,49.7 138.46,49.95 138.63,50.15 139.25,50.58 139.25,51.8 139.65,52.2 140.05,51.8 140.05,50.55 140.4,50.2 144.13,50.2 144.4,50.47 144.4,52.1 144.44,52.21 144.55,52.25 144.8,52.25 144.91,52.21 144.95,52.1 144.95,50.05 144.94,49.95 144.83,49.77 144.58,49.52 144.5,49.45 144.3,49.4 139.5,49.4 139.48,49.27 139.1,48.48 139.1,48.05 139.09,48.01 139.18,47.81 139.19,47.75 139.18,47.7 139.13,47.63 139.04,47.6 138.98,47.61 138.93,47.65 138.87,47.61 138.81,47.6 138.72,47.63 138.67,47.7
SIG100 on TOP: 158.71,52.7 158.65,52.71 158.61,52.74 158.45,52.9 158.08,52.9 157.22,52.75 157.17,52.75 156.65,52.75 156.1,53.3 156.65,53.85 157.17,53.85 157.22,53.85 157.26,53.84 158.08,53.7 158.45,53.7 158.61,53.86 158.65,53.89 158.71,53.9 159.25,53.9 159.36,53.86 159.4,53.75 159.4,52.85 159.36,52.74 159.25,52.7
SIG102 on TOP: 154.8,48.66 154.8,48.7 154.81,48.74 154.93,49.12 154.93,49.96 154.9,49.99 154.67,50.46 154.63,50.45 154.24,50.45 154.2,50.45 154.15,50.46 153.33,50.6 152,50.6 151.85,50.63 151.72,50.72 151.28,51.16 148.01,51.16 147.79,50.94 147.75,50.91 147.69,50.9 147.09,50.9 146.99,50.94 146.94,51.05 146.94,52.05 146.99,52.16 147.09,52.2 147.69,52.2 147.75,52.19 147.79,52.16 147.99,51.96 151.44,51.96 151.6,51.93 151.73,51.84 152.17,51.4 153.33,51.4 154.15,51.54 154.2,51.55 154.24,51.55 154.69,51.55 154.72,51.76 154.38,52.15 154.35,52.3 154.35,53.3 154.75,53.7 155.15,53.3 155.15,52.47 155.52,52.06 155.55,51.92 155.69,51.09 155.7,51.05 155.7,51 155.7,50.7 155.7,50.66 155.69,50.61 155.67,50.56 155.64,50.52 155.23,49.72 155.22,49.71 155.22,49.12 155.34,48.74 155.35,48.7 155.35,48.66 155.35,48.5 155.07,48.23 154.8,48.5
SIG104 on TOP: 151.6,43.25 151.49,43.29 151.45,43.4 151.45,47.4 151.49,47.51 151.6,47.55 151.7,47.85 151.3,48.25 150.12,48.25 149.95,48.32 149.88,48.5 149.88,49.07 149.7,49.25 146.7,49.25 146.6,49.27 146.52,49.32 145.76,50.09 145.7,50.17 145.69,50.27 145.69,51.56 145.94,51.81 146.19,51.56 146.19,50.37 146.8,49.75 149.8,49.75 149.9,49.73 149.98,49.68 150.3,49.35 150.36,49.27 150.38,49.17 150.38,48.9 150.53,48.75 151.4,48.75 151.5,48.73 151.58,48.68 152.13,48.13 152.18,48.05 152.2,47.95 152.2,47.86 152.29,47.55 152.3,47.55 152.41,47.51 152.45,47.4 152.45,46.7 153.1,46.05 154.25,46.05 154.36,46.01 154.4,45.9 154.4,45.75 154.36,45.64 154.25,45.6 153.1,45.6 152.45,44.95 152.45,43.4 152.41,43.29 152.3,43.25
SIG115 on TOP: 248.26,69 248.2,69.01 248.16,69.04 246.29,70.91 246.26,70.95 246.25,71.01 246.25,74.64 246.26,74.7 246.29,74.74 248.01,76.46 248.05,76.49 248.11,76.5 252.6,76.5 254.05,77.95 254.05,79.25 254.09,79.36 254.2,79.4 255,79.4 255.11,79.36 255.15,79.25 255.15,77 257.55,74.6 261.05,74.6 261.16,74.56 261.2,74.45 261.2,69.75 261.16,69.64 261.05,69.6 252.2,69.6 251.64,69.04 251.6,69.01 251.54,69
SIG115 on BOTTOM: 248.46,68.6 248.4,68.61 248.36,68.64 245.99,71.01 245.96,71.05 245.95,71.11 245.95,74.74 245.96,74.8 245.99,74.84 247.21,76.06 247.25,76.09 247.31,76.1 253.29,76.1 253.35,76.09 253.39,76.06 255.15,74.3 261.05,74.3 261.16,74.26 261.2,74.15 261.2,68.75 261.16,68.64 261.05,68.6
SIG141 on TOP: 292.25,37.69 291.83,38.1 292.25,38.52 292.41,38.52 292.46,38.51 292.52,38.5 293.06,38.36 297.7,43 297.7,43.14 297.71,43.2 297.74,43.24 297.81,43.31 297.85,43.34 297.91,43.35 298.05,43.35 300.25,45.55 300.33,45.61 300.43,45.62 304.07,45.62 304.21,45.76 304.25,45.79 304.31,45.8 304.59,45.8 304.7,45.76 304.74,45.65 304.74,45.1 304.7,44.99 304.59,44.95 304.29,44.95 304.23,44.96 304.18,44.99 304.05,45.12 300.53,45.12 298.38,42.97 298.38,42.86 298.37,42.8 298.33,42.76 298.32,42.74 298.27,42.71 298.21,42.7 298.1,42.7 293.33,37.92 293.25,37.87 293.15,37.85 293.11,37.85 292.52,37.7 292.46,37.69 292.41,37.69
SIG141 on TOP: 309.55,44.85 309.44,44.89 309.4,45 309.4,46.45 309.44,46.56 309.55,46.6 311.35,46.6 311.46,46.56 311.5,46.45 311.5,45 311.46,44.89 311.35,44.85
SIG141 on BOTTOM: 314.88,44.85 314.77,44.89 314.73,45 314.73,46.45 314.77,46.56 314.88,46.6 316.68,46.6 316.78,46.56 316.82,46.45 316.82,45 316.78,44.89 316.68,44.85
SIG141 on BOTTOM: 308.18,44.85 308.07,44.89 308.02,45 308.02,46.45 308.07,46.56 308.18,46.6 309.98,46.6 310.08,46.56 310.12,46.45 310.12,45 310.08,44.89 309.98,44.85
SIG199 on TOP: 75.8,25.75 64.96,25.75 64.41,25.2 60.88,25.2 60.87,28.74 62.16,30.02 62.25,30.11 62.35,30.19 62.35,41.26 61.94,42.48 62.09,42.79 62.41,42.64 62.54,42.25 62.66,42.25 62.79,42.64 63.11,42.79 63.26,42.48 62.85,41.26 62.85,32.2 64.3,30.75 76.83,30.75 77.79,30.56 78.6,30.02 79.88,28.74 79.88,25.2 76.35,25.2
SIG200 on CONDUCTIVE2 (solid shape): 60.18,19.11 60.24,19.37 60.5,19.43 63.18,18.45 63.3,18.36 63.35,18.21 63.24,18.01 63.01,17.98 62.49,18.17 61.44,17.12 61.63,16.6 61.48,16.28 61.16,16.43
SIG00232 on BOTTOM: 103.79,10.4 103.19,11 103.79,11.6 104.02,11.6 104.13,11.59 104.98,11.26 105.58,11.26 106.1,11.46 106.2,11.49 106.31,11.5 106.83,11.5 106.94,11.49 107.05,11.46 107.53,11.26 108.04,11.26 108.24,11.26 108.64,11.4 108.72,11.41 109.4,11.41 109.86,10.95 109.4,10.49 108.72,10.49 108.64,10.5 108.55,10.52 108.09,10.7 108.08,10.7 107.66,10.7 107.05,10.44 106.94,10.41 106.83,10.4 106.31,10.4 106.2,10.41 106.1,10.44 105.29,10.76 105.01,10.76 104.13,10.41 104.02,10.4
SIG00233 on TOP: 126.18,1.85 126.06,1.91 126.03,2.04 126.15,2.58 125.68,3.05 125.14,2.93 124.96,3.02 125.03,3.21 125.07,3.22 126.41,3.52 130.34,7.46 130.39,7.49 130.45,7.5 136.59,7.5 139.09,10.01 139.14,10.04 139.2,10.05 145.39,10.05 145.77,10.16 145.83,10.17 145.88,10.15 145.95,10.08 145.96,9.98 145.94,9.94 145.9,9.9 145.92,9.89 145.94,9.86 145.96,9.83 145.94,9.69 145.81,9.63 145.77,9.64 145.39,9.75 139.26,9.75 136.76,7.24 136.71,7.21 136.65,7.2 130.51,7.2 126.7,3.39 126.7,2 126.66,1.9 126.55,1.85
SIG00233 on CONDUCTIVE4: 146.13,9.74 145.93,9.68 145.87,9.89 145.9,9.95 145.84,9.92 145.63,9.98 145.69,10.18 146.22,10.48 147.15,11.41 147.18,11.46 147.18,40.18 147.01,40.76 147.12,40.95 147.3,40.84 147.32,40.76 147.53,40.95 147.64,40.76 147.47,40.18 147.47,11.46 147.45,11.34 147.4,11.24 147.38,11.22 146.43,10.27
SIG00234 on TOP: 131.27,2.95 130.69,3.23 130.21,2.94 130.01,2.99 130.05,3.2 130.06,3.2 131.2,3.89 131.96,5.45 132.09,5.6 132.28,5.65 137.64,5.65 139.19,7.21 139.24,7.24 139.3,7.25 145.39,7.25 145.77,7.36 145.84,7.37 145.9,7.34 145.95,7.29 145.96,7.22 145.95,7.15 145.9,7.1 145.95,7.05 145.96,6.98 145.9,6.86 145.77,6.84 145.39,6.95 139.36,6.95 137.81,5.39 137.76,5.36 137.7,5.35 132.28,5.35 132.25,5.34 132.23,5.32 131.47,3.76 131.64,2.43 131.64,2.41 131.5,2.26 131.34,2.39
SIG00234 on CONDUCTIVE4: 145.84,7.08 145.91,6.88 145.72,6.8 145.71,6.81 145.39,6.96 145.36,6.98 145.34,6.99 144.29,8.04 144.26,8.09 144.25,8.15 144.25,10.25 144.26,10.31 144.29,10.36 146.25,12.31 146.25,39.04 146.25,39.06 146.24,39.08 145.04,40.27 144.52,40.57 144.46,40.77 144.66,40.83 144.74,40.78 144.7,40.86 144.75,41.07 144.96,41.01 145.26,40.48 146.45,39.29 146.52,39.18 146.55,39.04 146.55,12.25 146.54,12.19 146.51,12.14 144.55,10.19 144.55,8.21 145.48,7.28 145.72,7.4 145.91,7.32 145.84,7.12 145.79,7.1
SIG00332 on BOTTOM: 239.24,41.78 238.93,41.62 238.77,41.93 238.94,42.54 238.63,42.85 238.02,42.68 237.99,42.67 237.95,42.67 237.71,42.88 237.87,43.15 237.88,43.16 239.3,43.57 243.09,47.36 243.14,47.39 243.2,47.4 248.2,47.4 248.38,47.33 248.45,47.15 248.45,46.3 248.38,46.12 248.2,46.05 242.49,46.05 239.66,43.21 239.25,41.79
SIG00333 on TOP: 150.85,120.19 150.09,120.95 149.5,120.95 149.39,120.99 149.35,121.1 149.35,121.6 149.39,121.71 149.5,121.75 150.8,121.75 151.41,122.36 151.45,122.39 151.51,122.4 152.4,122.4 152.51,122.36 152.55,122.25 152.55,119.66 152.54,119.6 152.51,119.56 151.4,118.45 151.4,117.51 151.12,117.23 150.85,117.51
SIG00334 on TOP: 141.95,116.6 141.84,116.64 141.8,116.75 141.8,118.3 141.84,118.41 141.95,118.45 143.65,118.45 143.76,118.41 143.8,118.3 143.8,116.75 143.76,116.64 143.65,116.6
SIG00335 on BOTTOM: 148.2,116.3 148.09,116.34 148.05,116.45 148.05,118.15 148.09,118.26 148.2,118.3 150.65,118.3 150.76,118.26 150.8,118.15 150.8,116.45 150.76,116.34 150.65,116.3
SIG00336 on TOP: 149.58,119.95 149.62,120.06 149.73,120.1 149.98,120.1 150.09,120.06 150.13,119.95 150.13,117.51 149.85,117.23 149.58,117.51
SIG00336 on BOTTOM: 151.75,116.9 151.64,116.94 151.6,117.05 151.6,118.25 151.1,118.75 149.7,118.75 149.59,118.79 149.55,118.9 149.55,120.04 149.56,120.1 149.59,120.14 150.06,120.61 150.1,120.64 150.16,120.65 158.05,120.65 158.16,120.61 158.2,120.5 158.2,119.85 158.16,119.74 158.05,119.7 156.8,119.7 156.64,119.54 156.6,119.51 156.54,119.5 154.71,119.5 154.65,119.51 154.61,119.54 154.55,119.6 153.1,119.6 152.4,118.9 152.4,117.05 152.36,116.94 152.25,116.9
SIG00342 on TOP, BOTTOM: 151.26,130.55 151.15,130.59 151.11,130.7 151.11,132.9 151.15,133.01 151.26,133.05 153.46,133.05 153.57,133.01 153.61,132.9 153.61,130.7 153.57,130.59 153.46,130.55
SIG00343 on TOP: 150.1,84.85 149.99,84.89 149.95,85 149.95,87.2 149.99,87.31 150.1,87.35 152.3,87.35 152.41,87.31 152.45,87.2 152.45,85 152.41,84.89 152.3,84.85
SIG00343 on TOP: 138.8,130.55 138.69,130.59 138.65,130.7 138.65,132.9 138.69,133.01 138.8,133.05 141,133.05 141.11,133.01 141.15,132.9 141.15,130.7 141.11,130.59 141,130.55
SIG00343 on BOTTOM: outline of 112 points within 133.65,53.05 222.16,133.1
SIG00345 on TOP: 162.25,73.35 162.14,73.39 162.1,73.5 162.1,75 162.14,75.11 162.25,75.15 164.45,75.15 164.56,75.11 164.6,75 164.6,73.5 164.56,73.39 164.45,73.35
SIG00345 on BOTTOM: 162.91,73.2 162.85,73.21 162.81,73.24 162.24,73.81 162.21,73.85 162.2,73.91 162.2,74.89 162.21,74.95 162.24,74.99 162.43,75.18 162.48,75.21 162.54,75.22 165.65,75.22 165.76,75.18 165.8,75.08 165.8,73.35 165.76,73.24 165.65,73.2
SIG00346 on TOP: 171.8,74 171.69,74.04 171.65,74.15 171.65,76.55 171.59,76.61 171.56,76.65 171.55,76.71 171.55,78.79 171.56,78.85 171.59,78.89 171.7,79 171.7,79.7 171.77,79.86 171.93,79.92 172.35,79.92 172.46,79.88 172.5,79.78 172.5,78.4 172.9,78 172.93,77.95 172.94,77.9 172.94,77.71 172.93,77.65 172.9,77.61 172.2,76.91 172.2,76.2 172.4,76 176.77,76 177.25,76.1 177.3,76.11 177.5,76.11 177.75,75.85 177.5,75.59 177.3,75.59 177.25,75.6 176.77,75.7 172.4,75.7 172.2,75.5 172.2,74.15 172.16,74.04 172.05,74
SIG00347 on TOP: 165.45,73.9 165.34,73.94 165.3,74.05 165.3,75.2 164.35,76.15 162.6,76.15 162.49,76.19 162.45,76.3 162.45,78.05 162,78.5 161.4,78.5 161.29,78.54 161.25,78.65 161.25,79.45 161.29,79.56 161.4,79.6 163.34,79.6 163.4,79.59 163.44,79.56 164.4,78.6 165.45,78.6 165.56,78.56 165.6,78.45 165.6,78.21 165.59,78.15 165.56,78.11 165.05,77.6 165.05,76.2 165.81,75.44 165.84,75.4 165.85,75.34 165.85,74.05 165.81,73.94 165.7,73.9
SIG00351 on TOP, BOTTOM: 155.54,84.85 155.43,84.89 155.39,85 155.39,87.2 155.43,87.31 155.54,87.35 157.74,87.35 157.85,87.31 157.89,87.2 157.89,85 157.85,84.89 157.74,84.85
SIG00352 on TOP, BOTTOM: 174.44,84.85 174.33,84.89 174.29,85 174.29,87.2 174.33,87.31 174.44,87.35 176.64,87.35 176.75,87.31 176.79,87.2 176.79,85 176.75,84.89 176.64,84.85
SIG00353 on BOTTOM: 179.3,71.9 179.19,71.94 179.15,72.05 179.15,72.39 179.16,72.45 179.19,72.49 179.2,72.75 179,72.95 178.14,72.95 177.5,72.76 177.44,72.74 177.37,72.74 176.23,72.74 176.17,72.74 176.1,72.76 175.46,72.95 173.21,72.95 173.15,72.96 173.11,72.99 172.69,73.41 172.66,73.45 172.65,73.51 172.65,74.69 172.66,74.75 172.69,74.79 172.9,75 172.9,75.45 172.7,75.65 169.86,75.65 169.8,75.66 169.76,75.69 169.69,75.76 169.66,75.8 169.65,75.86 169.65,76.04 169.66,76.1 169.69,76.14 169.76,76.21 169.8,76.24 169.86,76.25 173.47,76.25 173.58,76.21 173.62,76.1 173.62,75.56 173.62,75.52 173.51,74.96 173.51,73.74 173.8,73.45 175.46,73.45 176.1,73.64 176.17,73.66 176.23,73.66 177.37,73.66 177.44,73.66 177.5,73.64 178.14,73.45 179.1,73.45 179.2,73.43 179.63,73.03 179.68,72.95 179.7,72.85 179.7,72.5 179.74,72.45 179.75,72.39 179.75,72.05 179.71,71.94 179.6,71.9
SIG00354 on BOTTOM: 169.3,73.2 169.19,73.24 169.15,73.35 169.15,74.9 169.19,75.01 169.3,75.05 171.64,75.05 171.7,75.04 171.74,75.01 171.91,74.84 171.94,74.8 171.95,74.74 171.95,73.51 171.94,73.45 171.91,73.41 171.74,73.24 171.7,73.21 171.64,73.2
SIG00356 on TOP, BOTTOM: 133.36,130.55 133.25,130.59 133.21,130.7 133.21,132.9 133.25,133.01 133.36,133.05 135.56,133.05 135.67,133.01 135.71,132.9 135.71,130.7 135.67,130.59 135.56,130.55
SIG00360 on TOP: 161.7,67.65 161.59,67.69 161.55,67.8 161.55,69.39 161.56,69.45 161.59,69.49 162.11,70.01 162.15,70.04 162.21,70.05 164.45,70.05 164.56,70.01 164.6,69.9 164.6,68.31 164.59,68.25 164.56,68.21 164.04,67.69 164,67.66 163.94,67.65
SIG00361 on TOP: 164.46,65.95 164.4,65.96 164.36,65.99 163.94,66.41 163.91,66.45 163.9,66.51 163.9,66.99 163.91,67.05 163.94,67.09 164.36,67.51 164.4,67.54 164.46,67.55 165.04,67.55 165.3,67.81 165.3,69.65 165.34,69.76 165.45,69.8 165.7,69.8 165.81,69.76 165.85,69.65 165.85,68.3 167.1,67.05 167.45,67.05 167.56,67.01 167.6,66.9 167.6,66.71 167.59,66.65 167.56,66.61 167.3,66.35 167.25,66.31 167.19,66.3 165.4,66.3 165.09,65.99 165.05,65.96 164.99,65.95
SIG00362 on TOP: 145.77,119.3 145.09,119.98 145.06,120.02 145.05,120.08 145.05,120.62 145.06,120.68 145.09,120.72 145.77,121.4 145.77,123.05 145.61,123.21 145.58,123.25 145.57,123.31 145.57,123.6 145.61,123.71 145.72,123.75 146.35,123.75 146.46,123.71 146.5,123.6 146.5,123.31 146.49,123.25 146.46,123.21 146.32,123.07 146.32,117.51 146.04,117.23 145.77,117.51
SIG00362 on TOP, BOTTOM: 144.24,130.55 144.13,130.59 144.09,130.7 144.09,132.9 144.13,133.01 144.24,133.05 146.44,133.05 146.55,133.01 146.59,132.9 146.59,130.7 146.55,130.59 146.44,130.55
SIG00362 on TOP, BOTTOM: 156.7,130.55 156.59,130.59 156.55,130.7 156.55,132.9 156.59,133.01 156.7,133.05 158.9,133.05 159.01,133.01 159.05,132.9 159.05,130.7 159.01,130.59 158.9,130.55
SIG00362 on CONDUCTIVE2, CONDUCTIVE5: 143,116.55 142.93,116.58 142.9,116.65 142.9,117.8 142.69,118.29 142.2,118.5 139.94,118.5 139.9,118.51 139.87,118.53 135.83,122.57 135.81,122.6 135.8,122.64 135.8,127.21 135.81,127.25 135.83,127.28 136.37,127.82 136.4,127.84 136.44,127.85 142.8,127.85 144.05,129.1 144.05,132.95 144.08,133.02 144.15,133.05 146.5,133.05 146.57,133.02 146.6,132.95 146.6,119.94 146.59,119.9 146.57,119.87 146.35,119.65 146.35,116.65 146.32,116.58 146.25,116.55
SIG00362 on CONDUCTIVE3: 157.35,107.6 157.28,107.63 157.25,107.7 157.25,111.95 157.38,112.62 157.76,113.19 160.6,116.02 160.6,120.88 155.23,126.25 145.4,126.25 144.73,126.38 144.16,126.76 144.1,126.82 143.72,127.39 143.59,128.06 143.59,131.8 145.34,133.55 147.09,131.8 147.09,130.4 147.74,129.75 155.4,129.75 156.05,130.4 156.05,131.8 157.8,133.55 159.55,131.8 159.55,126.87 163.59,122.84 163.97,122.27 164.1,121.6 164.1,115.3 163.97,114.63 163.59,114.06 160.75,111.23 160.75,107.7 160.72,107.63 160.65,107.6
SIG00429 on BOTTOM: 253.04,118.55 252.94,118.57 252.86,118.62 252.67,118.81 252.62,118.89 252.6,118.99 252.6,122.7 251.06,124.24 244.61,124.24 244.55,124.25 244.51,124.28 244.39,124.4 244.36,124.44 244.35,124.5 244.35,125.01 244.39,125.12 244.5,125.16 251.62,125.16 251.71,125.14 251.79,125.09 253.38,123.5 253.43,123.42 253.45,123.33 253.49,123.25 253.5,123.17 253.5,119.6 254,119.1 254.8,119.1 254.98,119.03 255.05,118.85 255.05,118.8 254.98,118.62 254.8,118.55
SIG00438 on BOTTOM: 256.9,75.45 256.79,75.49 256.75,75.6 256.75,78.05 255.6,79.2 254.4,79.2 254.29,79.24 254.25,79.35 254.25,79.6 254.29,79.71 254.4,79.75 255.8,79.75 256.46,80.41 256.5,80.44 256.56,80.45 257.65,80.45 257.76,80.41 257.8,80.3 257.8,80.16 257.79,80.1 257.76,80.06 257.55,79.85 257.55,77 258.11,76.44 258.14,76.4 258.15,76.34 258.15,75.6 258.11,75.49 258,75.45
SIG00439 on BOTTOM: 262.6,124.35 262.49,124.39 262.45,124.5 262.45,129.25 262.39,129.31 262.36,129.35 262.35,129.41 262.35,130 262.39,130.11 262.5,130.15 263.25,130.15 263.36,130.11 263.4,130 263.4,129.35 263.76,128.99 264.45,128.99 264.56,128.94 264.6,128.84 264.6,126.86 264.59,126.8 264.56,126.76 263.6,125.8 263.6,124.5 263.56,124.39 263.45,124.35
